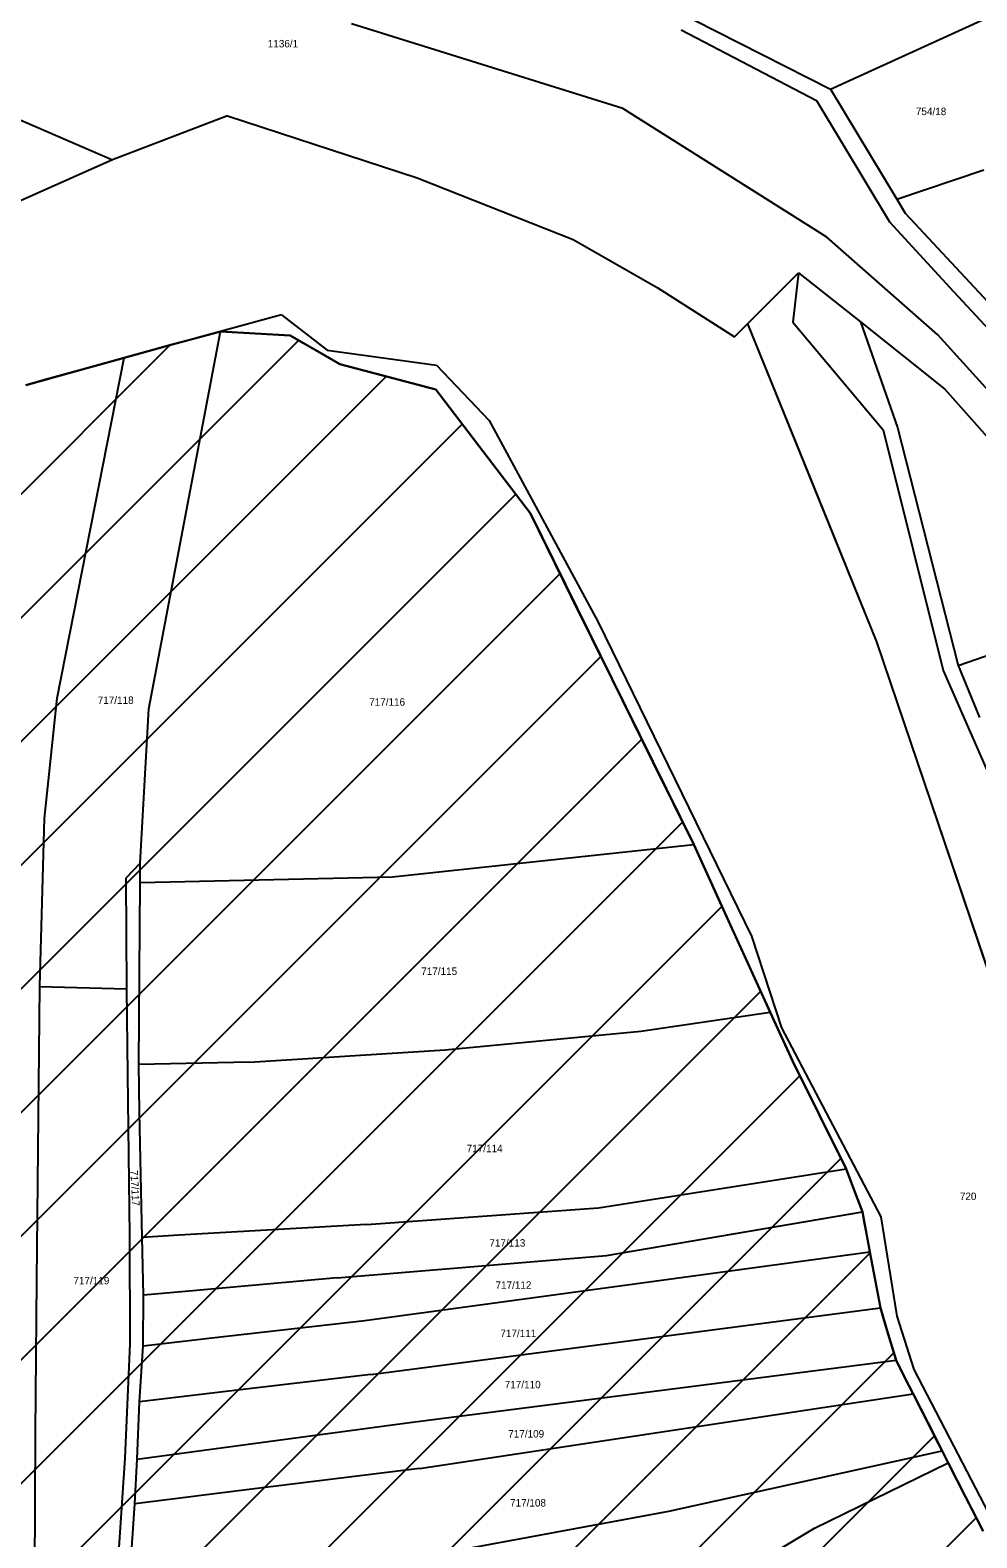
# Model space of a CAD drawing. Extents: x -593358 to -590116, y -1072518 to -1068420.
# Drawn here: x -591376.8 to -591160.3, y -1070135.4 to -1069790.6 of the extents above; entities that cross this region are included whole.
import ezdxf

# ---------------------------------------------------------------- set-up
doc = ezdxf.new("R2010")
doc.units = 0
for name, color, linetype in [('lesy', 7, 'Continuous'), ('Parcela KN', 7, 'Continuous'), ('Parcela ZE', 7, 'Continuous'), ('Parcelní číslo', 7, 'Continuous'), ('Vnitřní obvod', 7, 'Continuous'), ('zastavitelné území', 7, 'Continuous'), ('Železnice', 7, 'Continuous')]:
    doc.layers.add(name, color=color, linetype=linetype)

msp = doc.modelspace()

# ---------------------------------------------------------------- linework, layer by layer
at = {"layer": 'lesy'}
msp.add_lwpolyline([(-591212.79, -1069857.75), (-591198.02, -1069894.135), (-591183.25, -1069930.52), (-591167.595, -1069976.815), (-591151.94, -1070023.11), (-591129.64, -1070067.72), (-591110.56, -1070116.05), (-591089.65, -1070144.71), (-591065.54, -1070167.98), (-591041.43, -1070191.25), (-591019.12, -1070221.28), (-591006.76, -1070228.8), (-590996.76, -1070238.25)], dxfattribs=at)
at = {"layer": 'Parcela KN'}
for p, q in [((-591225.07, -1069788.18), (-591193.78, -1069804.04)), ((-591227.96, -1069790.52), (-591197.03, -1069806.66)), ((-591197.03, -1069806.66), (-591180.3, -1069834.39)), ((-591193.78, -1069804.04), (-591178.65, -1069829.26)), ((-591380.71, -1069810.4), (-591357.96, -1069820.23)), ((-591331.7, -1069810.15), (-591357.96, -1069820.23)), ((-591331.7, -1069810.15), (-591288.34, -1069824.34)), ((-591357.96, -1069820.23), (-591407.62, -1069842.19)), ((-591288.34, -1069824.34), (-591252.65, -1069838.42)), ((-591178.65, -1069829.26), (-591176.73, -1069832.46)), ((-591180.3, -1069834.39), (-591165.68, -1069850.31)), ((-591176.73, -1069832.46), (-591142.31, -1069869.42)), ((-591252.65, -1069838.42), (-591233.47, -1069849.45)), ((-591212.79, -1069857.75), (-591201.13, -1069846.09)), ((-591201.13, -1069846.09), (-591202.44, -1069857.37)), ((-591201.13, -1069846.09), (-591186.98, -1069857.31)), ((-591233.47, -1069849.45), (-591215.73, -1069860.69)), ((-591165.68, -1069850.31), (-591148.3, -1069869.06)), ((-591319.37, -1069855.7), (-591333.29, -1069859.47)), ((-591319.37, -1069855.7), (-591308.86, -1069863.73)), ((-591215.73, -1069860.69), (-591212.79, -1069857.75)), ((-591212.79, -1069857.75), (-591183.25, -1069930.52)), ((-591202.44, -1069857.37), (-591181.78, -1069881.96)), ((-591186.98, -1069857.31), (-591178.47, -1069881.43)), ((-591186.98, -1069857.31), (-591167.63, -1069872.65)), ((-591333.29, -1069859.47), (-591355.32, -1069865.54)), ((-591317.36, -1069860.44), (-591333.29, -1069859.47)), ((-591305.98, -1069866.94), (-591317.36, -1069860.44)), ((-591355.32, -1069865.54), (-591377.81, -1069871.74)), ((-591308.86, -1069863.73), (-591283.88, -1069867.18)), ((-591284.05, -1069872.76), (-591305.98, -1069866.94)), ((-591283.88, -1069867.18), (-591271.88, -1069879.84)), ((-591262.43, -1069901.16), (-591284.05, -1069872.76)), ((-591167.63, -1069872.65), (-591146.9, -1069896.12)), ((-591271.88, -1069879.84), (-591246.93, -1069925.96)), ((-591181.78, -1069881.96), (-591168.01, -1069937.03)), ((-591178.47, -1069881.43), (-591164.59, -1069935.89)), ((-591225.08, -1069976.85), (-591262.43, -1069901.16)), ((-591246.93, -1069925.96), (-591211.87, -1069997.82)), ((-591183.25, -1069930.52), (-591151.94, -1070023.11)), ((-591168.01, -1069937.03), (-591157.47, -1069961.25)), ((-591164.59, -1069935.89), (-591159.72, -1069947.79)), ((-591207.61, -1070015.17), (-591225.08, -1069976.85)), ((-591211.87, -1069997.82), (-591205.03, -1070018.79)), ((-591202.45, -1070026.49), (-591207.61, -1070015.17)), ((-591205.03, -1070018.79), (-591182.28, -1070062.02)), ((-591190.22, -1070051.02), (-591202.45, -1070026.49)), ((-591186.51, -1070060.88), (-591190.22, -1070051.02)), ((-591184.79, -1070070.05), (-591186.51, -1070060.88)), ((-591182.28, -1070062.02), (-591178.62, -1070084.76)), ((-591182.4, -1070082.82), (-591184.79, -1070070.05)), ((-591178.8, -1070094.83), (-591182.4, -1070082.82)), ((-591178.62, -1070084.76), (-591174.75, -1070096.93)), ((-591174.9, -1070102.5), (-591178.8, -1070094.83)), ((-591174.75, -1070096.93), (-591155.64, -1070133.77)), ((-591168.25, -1070115.57), (-591174.9, -1070102.5)), ((-591166.89, -1070118.25), (-591168.25, -1070115.57)), ((-591158.91, -1070133.9), (-591166.89, -1070118.25))]:
    msp.add_line(p, q, dxfattribs=at)
at = {"layer": 'Parcela ZE'}
for p, q in [((-591193.78, -1069804.04), (-591107.78, -1069764.88)), ((-591178.65, -1069829.26), (-591158.72, -1069822.54)), ((-591349.64, -1069945.83), (-591333.29, -1069859.47)), ((-591370.6, -1069943.36), (-591355.32, -1069865.54)), ((-591164.59, -1069935.89), (-591127.23, -1069922.98)), ((-591373.56, -1069970.92), (-591370.6, -1069943.36)), ((-591351.66, -1069981.1), (-591349.64, -1069945.83)), ((-591374.48, -1070003.73), (-591373.56, -1069970.92)), ((-591293.97, -1069984.24), (-591225.08, -1069976.85)), ((-591351.66, -1069981.1), (-591354.94, -1069984.52)), ((-591351.69, -1069985.52), (-591351.66, -1069981.1)), ((-591354.94, -1069984.52), (-591354.8, -1070009.87)), ((-591351.99, -1070027.18), (-591351.69, -1069985.52)), ((-591351.69, -1069985.52), (-591293.97, -1069984.24)), ((-591374.63, -1070009.36), (-591374.48, -1070003.73)), ((-591375.3, -1070076.48), (-591374.63, -1070009.36)), ((-591374.63, -1070009.36), (-591354.8, -1070009.87)), ((-591354.8, -1070009.87), (-591354.55, -1070029.37)), ((-591237.18, -1070019.52), (-591207.61, -1070015.17)), ((-591281.94, -1070023.85), (-591237.18, -1070019.52)), ((-591326.62, -1070026.61), (-591281.94, -1070023.85)), ((-591326.62, -1070026.61), (-591351.99, -1070027.18)), ((-591351.77, -1070038.1), (-591351.99, -1070027.18)), ((-591354.55, -1070029.37), (-591354.09, -1070066.32)), ((-591351.18, -1070066.71), (-591351.77, -1070038.1)), ((-591246.87, -1070059.96), (-591190.22, -1070051.02)), ((-591299.9, -1070063.77), (-591246.87, -1070059.96)), ((-591244.99, -1070070.84), (-591186.51, -1070060.88)), ((-591299.9, -1070063.77), (-591342.78, -1070066.23)), ((-591354.09, -1070066.32), (-591354.03, -1070091.08)), ((-591342.78, -1070066.23), (-591351.18, -1070066.71)), ((-591350.89, -1070079.97), (-591351.18, -1070066.71)), ((-591306.64, -1070075.95), (-591244.99, -1070070.84)), ((-591300.29, -1070085.76), (-591184.79, -1070070.05)), ((-591306.64, -1070075.95), (-591338.74, -1070078.87)), ((-591375.62, -1070111.37), (-591375.3, -1070076.48)), ((-591338.74, -1070078.87), (-591350.89, -1070079.97)), ((-591350.97, -1070091.51), (-591350.89, -1070079.97)), ((-591298.91, -1070098.06), (-591182.4, -1070082.82)), ((-591335.27, -1070089.73), (-591300.29, -1070085.76)), ((-591350.97, -1070091.51), (-591335.27, -1070089.73)), ((-591354.03, -1070091.08), (-591355.15, -1070117.2)), ((-591351.79, -1070104.37), (-591350.97, -1070091.51)), ((-591290.62, -1070109.17), (-591178.8, -1070094.83)), ((-591298.91, -1070098.06), (-591331.37, -1070101.93)), ((-591331.37, -1070101.93), (-591351.79, -1070104.37)), ((-591287.8, -1070119.56), (-591174.9, -1070102.5)), ((-591352.35, -1070117.44), (-591351.79, -1070104.37)), ((-591327.49, -1070114.11), (-591290.62, -1070109.17)), ((-591375.8, -1070149.77), (-591375.62, -1070111.37)), ((-591352.35, -1070117.44), (-591327.49, -1070114.11)), ((-591355.15, -1070117.2), (-591357.82, -1070157.55)), ((-591352.9, -1070127.69), (-591352.35, -1070117.44)), ((-591230.77, -1070129.32), (-591168.25, -1070115.57)), ((-591287.8, -1070119.56), (-591324.29, -1070124.11)), ((-591197.5, -1070133.22), (-591166.89, -1070118.25)), ((-591324.29, -1070124.11), (-591352.9, -1070127.69)), ((-591354.44, -1070150.92), (-591352.9, -1070127.69)), ((-591281.83, -1070138.77), (-591230.77, -1070129.32)), ((-591237.74, -1070157.37), (-591197.5, -1070133.22))]:
    msp.add_line(p, q, dxfattribs=at)
at = {"layer": 'Vnitřní obvod'}
for p, q in [((-591344.305, -1069862.505), (-591349.812, -1069864.022)), ((-591338.797, -1069860.988), (-591344.305, -1069862.505)), ((-591333.29, -1069859.47), (-591338.797, -1069860.988)), ((-591325.325, -1069859.955), (-591333.29, -1069859.47)), ((-591321.343, -1069860.198), (-591325.325, -1069859.955)), ((-591317.36, -1069860.44), (-591321.343, -1069860.198)), ((-591314.515, -1069862.065), (-591317.36, -1069860.44)), ((-591311.67, -1069863.69), (-591314.515, -1069862.065)), ((-591355.32, -1069865.54), (-591360.943, -1069867.09)), ((-591349.812, -1069864.022), (-591355.32, -1069865.54)), ((-591305.98, -1069866.94), (-591311.67, -1069863.69)), ((-591366.565, -1069868.64), (-591372.188, -1069870.19)), ((-591360.943, -1069867.09), (-591366.565, -1069868.64)), ((-591300.498, -1069868.395), (-591305.98, -1069866.94)), ((-591295.015, -1069869.85), (-591300.498, -1069868.395)), ((-591372.188, -1069870.19), (-591377.81, -1069871.74)), ((-591289.532, -1069871.305), (-591295.015, -1069869.85)), ((-591284.05, -1069872.76), (-591289.532, -1069871.305)), ((-591278.645, -1069879.86), (-591284.05, -1069872.76)), ((-591273.24, -1069886.96), (-591278.645, -1069879.86)), ((-591267.835, -1069894.06), (-591273.24, -1069886.96)), ((-591262.43, -1069901.16), (-591267.835, -1069894.06)), ((-591253.093, -1069920.083), (-591262.43, -1069901.16)), ((-591243.755, -1069939.005), (-591253.093, -1069920.083)), ((-591234.417, -1069957.927), (-591243.755, -1069939.005)), ((-591225.08, -1069976.85), (-591234.417, -1069957.927)), ((-591216.345, -1069996.01), (-591225.08, -1069976.85)), ((-591211.978, -1070005.59), (-591216.345, -1069996.01)), ((-591207.61, -1070015.17), (-591211.978, -1070005.59)), ((-591205.03, -1070020.83), (-591207.61, -1070015.17)), ((-591202.45, -1070026.49), (-591205.03, -1070020.83)), ((-591199.392, -1070032.623), (-591202.45, -1070026.49)), ((-591196.335, -1070038.755), (-591199.392, -1070032.623)), ((-591193.277, -1070044.887), (-591196.335, -1070038.755)), ((-591190.22, -1070051.02), (-591193.277, -1070044.887)), ((-591188.365, -1070055.95), (-591190.22, -1070051.02)), ((-591186.51, -1070060.88), (-591188.365, -1070055.95)), ((-591186.08, -1070063.173), (-591186.51, -1070060.88)), ((-591185.65, -1070065.465), (-591186.08, -1070063.173)), ((-591185.22, -1070067.758), (-591185.65, -1070065.465)), ((-591184.79, -1070070.05), (-591185.22, -1070067.758)), ((-591184.193, -1070073.242), (-591184.79, -1070070.05)), ((-591183.595, -1070076.435), (-591184.193, -1070073.242)), ((-591182.998, -1070079.627), (-591183.595, -1070076.435)), ((-591182.4, -1070082.82), (-591182.998, -1070079.627)), ((-591181.5, -1070085.823), (-591182.4, -1070082.82)), ((-591180.6, -1070088.825), (-591181.5, -1070085.823)), ((-591179.7, -1070091.828), (-591180.6, -1070088.825)), ((-591178.8, -1070094.83), (-591179.7, -1070091.828)), ((-591176.85, -1070098.665), (-591178.8, -1070094.83)), ((-591175.875, -1070100.583), (-591176.85, -1070098.665)), ((-591174.9, -1070102.5), (-591175.875, -1070100.583)), ((-591173.238, -1070105.768), (-591174.9, -1070102.5)), ((-591171.575, -1070109.035), (-591173.238, -1070105.768)), ((-591169.912, -1070112.302), (-591171.575, -1070109.035)), ((-591168.25, -1070115.57), (-591169.912, -1070112.302)), ((-591167.91, -1070116.24), (-591168.25, -1070115.57)), ((-591167.57, -1070116.91), (-591167.91, -1070116.24)), ((-591167.23, -1070117.58), (-591167.57, -1070116.91)), ((-591166.89, -1070118.25), (-591167.23, -1070117.58)), ((-591164.895, -1070122.163), (-591166.89, -1070118.25)), ((-591162.9, -1070126.075), (-591164.895, -1070122.163)), ((-591160.905, -1070129.988), (-591162.9, -1070126.075)), ((-591158.91, -1070133.9), (-591160.905, -1070129.988))]:
    msp.add_line(p, q, dxfattribs=at)
at = {"layer": 'zastavitelné území'}
for p, q in [((-591555.77, -1070101.87), (-591315.438, -1069861.538)), ((-591559.544, -1070077.359), (-591344.836, -1069862.651)), ((-591555.899, -1070130.283), (-591295.371, -1069869.755)), ((-591568.102, -1070170.77), (-591278.017, -1069880.685)), ((-591566.586, -1070197.538), (-591265.792, -1069896.744)), ((-591564.758, -1070223.995), (-591255.654, -1069914.891)), ((-591562.934, -1070250.455), (-591246.309, -1069933.83)), ((-591546.732, -1070262.537), (-591236.963, -1069952.769)), ((-591546.693, -1070290.782), (-591227.618, -1069971.707)), ((-591530.725, -1070303.099), (-591218.628, -1069991.002)), ((-591530.106, -1070330.765), (-591209.771, -1070010.429)), ((-591520.522, -1070349.464), (-591200.819, -1070029.761)), ((-591509.234, -1070366.46), (-591191.409, -1070048.635)), ((-591511.223, -1070396.734), (-591184.75, -1070070.261)), ((-591535.698, -1070449.493), (-591179.315, -1070093.111)), ((-591513.288, -1070455.368), (-591170.017, -1070112.097)), ((-591467.818, -1070438.181), (-591160.472, -1070130.836))]:
    msp.add_line(p, q, dxfattribs=at)
msp.add_lwpolyline([(-591377.81, -1069871.74), (-591366.565, -1069868.64), (-591355.32, -1069865.54), (-591344.305, -1069862.505), (-591333.29, -1069859.47), (-591325.325, -1069859.955), (-591317.36, -1069860.44), (-591311.67, -1069863.69), (-591305.98, -1069866.94), (-591295.015, -1069869.85), (-591284.05, -1069872.76), (-591273.24, -1069886.96), (-591262.43, -1069901.16), (-591243.755, -1069939.005), (-591225.08, -1069976.85), (-591216.345, -1069996.01), (-591207.61, -1070015.17), (-591202.45, -1070026.49), (-591196.335, -1070038.755), (-591190.22, -1070051.02), (-591188.365, -1070055.95), (-591186.51, -1070060.88), (-591185.65, -1070065.465), (-591184.79, -1070070.05), (-591183.595, -1070076.435), (-591182.4, -1070082.82), (-591180.6, -1070088.825), (-591178.8, -1070094.83), (-591176.85, -1070098.665), (-591174.9, -1070102.5), (-591171.575, -1070109.035), (-591168.25, -1070115.57), (-591167.57, -1070116.91), (-591166.89, -1070118.25), (-591162.9, -1070126.075), (-591158.91, -1070133.9)], dxfattribs=at)
at = {"layer": 'Železnice'}
msp.add_lwpolyline([(-590479.902, -1070355.312), (-590561.189, -1070408.628), (-590635.503, -1070432.744), (-590680.945, -1070437.517), (-590764.548, -1070426.966), (-590856.186, -1070387.527), (-590911.168, -1070343.816), (-590951.84, -1070284.28), (-591000.043, -1070177.014), (-591072.823, -1070015.059), (-591113.272, -1069933.844), (-591136.37, -1069896.665), (-591169.259, -1069860.24), (-591194.616, -1069837.882), (-591241.313, -1069808.491), (-591303.325, -1069789.148)], dxfattribs=at)

# ---------------------------------------------------------------- texts
at = {"layer": 'Parcelní číslo'}
for s, p in [('1136/1', (-591322.475, -1069794.5)), ('754/18', (-591174.291, -1069810)), ('717/118', (-591361.367, -1069944.69)), ('717/116', (-591299.287, -1069945.09)), ('717/115', (-591287.384, -1070006.68)), ('717/114', (-591276.997, -1070047.23)), ('720', (-591164.234, -1070058.17)), ('717/113', (-591271.804, -1070068.83)), ('717/119', (-591366.917, -1070077.45)), ('717/112', (-591270.411, -1070078.48)), ('717/111', (-591269.299, -1070089.52)), ('717/110', (-591268.294, -1070101.24)), ('717/109', (-591267.492, -1070112.5)), ('717/108', (-591267.082, -1070128.28))]:
    msp.add_text(s, height=1.7, dxfattribs=at).set_placement(p)
msp.add_text('717/117', height=1.7, rotation=273.01439, dxfattribs=at).set_placement((-591353.892, -1070051.378))

doc.saveas('drawing.dxf')
